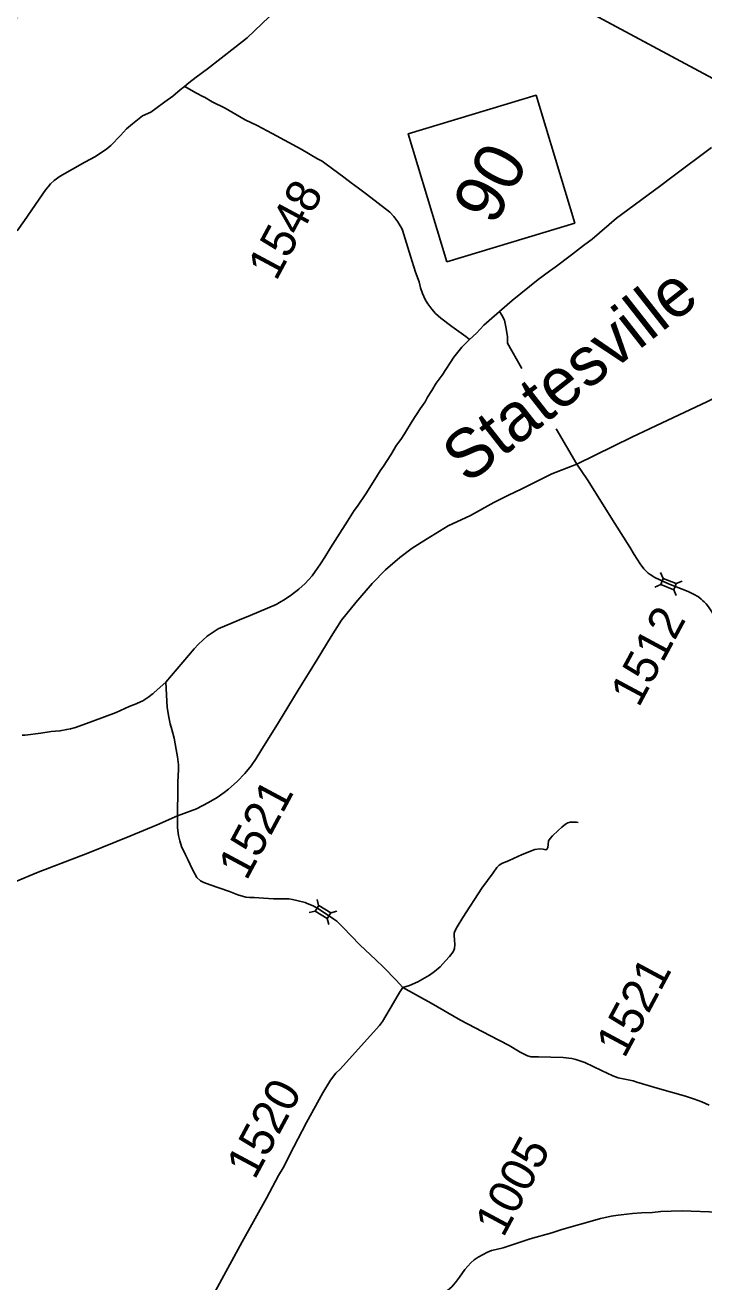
# Model space of a CAD drawing. Extents: x 1376167 to 1379209, y 761324 to 763997.
# Drawn here: x 1376608.1 to 1376691.6, y 762860.1 to 763014.5 of the extents above; entities that cross this region are included whole.
import ezdxf

# ---------------------------------------------------------------- set-up
doc = ezdxf.new("R2010")
doc.units = 0
for name, color, linetype in [('Default', 7, 'Continuous'), ('Old_Level_1', 7, 'Continuous'), ('Sheet Data Field CELL', 7, 'Continuous')]:
    doc.layers.add(name, color=color, linetype=linetype)

msp = doc.modelspace()

# ---------------------------------------------------------------- linework, layer by layer
at = {"layer": 'Default'}
for p, q in [((1376671.18, 762983.24), (1376672.6, 762984.28)), ((1376667.99, 762980.66), (1376671.18, 762983.24)), ((1376666.42, 762979.32), (1376667.99, 762980.66)), ((1376662.5, 762976.1), (1376662.31, 762976.25)), ((1376662.74, 762975.9), (1376662.5, 762976.1)), ((1376677.25, 762958.65), (1376675.94, 762960.58)), ((1376680.6, 762953.27), (1376677.25, 762958.65)), ((1376686.55, 762946.51), (1376686.24, 762947.23)), ((1376686.25, 762945.78), (1376685.53, 762945.46)), ((1376688.17, 762944.41), (1376687.86, 762945.13)), ((1376688.88, 762946.19), (1376688.16, 762945.88)), ((1376644.2, 762906.31), (1376644.02, 762907.08)), ((1376643.79, 762905.64), (1376643.02, 762905.45)), ((1376645.45, 762903.97), (1376645.26, 762904.73)), ((1376646.45, 762905.61), (1376645.69, 762905.42))]:
    msp.add_line(p, q, dxfattribs=at)
for points in [[(1376648.76, 763029.08), (1376648.29, 763028.55), (1376648, 763028.24), (1376647.83, 763028.06), (1376646.1, 763025.98), (1376643.79, 763022.92), (1376642.92, 763021.74), (1376641.74, 763020.29), (1376640.75, 763018.98), (1376640.14, 763018.1), (1376639.06, 763016.64), (1376638.1, 763015.54), (1376635.43, 763012.95), (1376633.91, 763011.77), (1376630.52, 763009.14), (1376629.15, 763008.11), (1376628.26, 763007.42), (1376627.71, 763006.98)], [(1376627.71, 763006.98), (1376627.16, 763006.56), (1376626.28, 763005.8), (1376625.29, 763005.09), (1376624.2, 763004.26), (1376623.57, 763003.82), (1376622.54, 763003.36), (1376621.31, 763002.38), (1376620.6, 763001.76), (1376619.85, 763000.97), (1376618.64, 762999.74), (1376618.16, 762999.32), (1376616.75, 762998.37), (1376615.46, 762997.66), (1376612.44, 762995.95), (1376611.69, 762995.44), (1376611.25, 762995.02), (1376610.96, 762994.64), (1376610.68, 762994.3), (1376608.02, 762990.52), (1376607.13, 762989.22)], [(1376630.03, 763005.72), (1376629.12, 763006.19), (1376628.04, 763006.81), (1376627.71, 763006.98)], [(1376632.69, 763004.31), (1376631.13, 763005.11), (1376630.17, 763005.65), (1376630.03, 763005.72)], [(1376635.15, 763002.87), (1376632.69, 763004.31)], [(1376644.07, 762998.1), (1376642.06, 762999.26), (1376638.5, 763001.2), (1376636.66, 763002.19), (1376635.15, 763002.87)], [(1376672.6, 762984.28), (1376673.27, 762984.79), (1376675.3, 762986.31), (1376676.78, 762987.43), (1376677.83, 762988.21), (1376680.82, 762990.8), (1376686.12, 762994.69), (1376687.79, 762995.97), (1376692.48, 762999.48)], [(1376647.29, 762995.82), (1376645.14, 762997.43), (1376644.62, 762997.79), (1376644.07, 762998.1)], [(1376658.57, 762979.07), (1376658.1, 762979.63), (1376657.62, 762980.26), (1376657.28, 762980.81), (1376656.95, 762981.55), (1376656.73, 762982.24), (1376656.54, 762982.96), (1376656.1, 762984.16), (1376655.51, 762986.12), (1376654.5, 762989.33), (1376654.35, 762989.67), (1376654.22, 762989.85), (1376653.94, 762990.35), (1376653.43, 762991.02), (1376652.96, 762991.52), (1376650.08, 762993.74), (1376649.09, 762994.49), (1376648.19, 762995.12), (1376647.29, 762995.82)], [(1376675.94, 762960.58), (1376682.69, 762963.88), (1376684.96, 762964.96), (1376691.99, 762968.25), (1376694.26, 762969.38), (1376696.28, 762970.78), (1376697.97, 762972.31), (1376699.64, 762974.04), (1376700.98, 762975.67), (1376702.88, 762978.32), (1376704.6, 762980.94), (1376709.52, 762988.1), (1376712.73, 762992.97), (1376713.7, 762994.26)], [(1376662.31, 762976.25), (1376660.58, 762977.5), (1376659.22, 762978.49), (1376658.57, 762979.07)], [(1376662.74, 762975.9), (1376663.59, 762976.68), (1376664.53, 762977.64), (1376665.16, 762978.23), (1376666.42, 762979.32)], [(1376667.43, 762975.44), (1376667.4, 762976.25), (1376667.2, 762977.44), (1376667.04, 762978.25), (1376666.73, 762978.88), (1376666.42, 762979.32)], [(1376657.28, 762968.22), (1376657.59, 762968.8), (1376658.11, 762969.62), (1376658.66, 762970.5), (1376659.39, 762971.52), (1376660.82, 762973.71), (1376661.8, 762974.94), (1376662.74, 762975.9)], [(1376669.17, 762972.32), (1376667.43, 762975.44)], [(1376654.75, 762964.28), (1376655.72, 762965.83), (1376656.7, 762967.35), (1376657.28, 762968.22)], [(1376675.94, 762960.58), (1376673.42, 762964.91)], [(1376648.57, 762954.88), (1376648.99, 762955.42), (1376649.99, 762956.92), (1376651.09, 762958.66), (1376651.76, 762959.75), (1376652.17, 762960.31), (1376653.06, 762961.71), (1376653.79, 762962.89), (1376654.31, 762963.59), (1376654.75, 762964.28)], [(1376665.72, 762955.85), (1376667.56, 762956.74), (1376669.11, 762957.49), (1376671.06, 762958.46), (1376672.88, 762959.36), (1376675.94, 762960.58)], [(1376650.79, 762945.89), (1376652.43, 762947.59), (1376654.2, 762949.11), (1376655.71, 762950.23), (1376657.46, 762951.36), (1376660.11, 762952.99), (1376662.89, 762954.26), (1376665.72, 762955.85)], [(1376645.64, 762950.29), (1376646.51, 762951.62), (1376647.76, 762953.57), (1376648.57, 762954.88)], [(1376687.2, 762945.84), (1376685.53, 762946.62), (1376684.95, 762947.01), (1376684.73, 762947.17), (1376684.18, 762947.72), (1376683.73, 762948.31), (1376683, 762949.47), (1376682.47, 762950.38), (1376680.6, 762953.27)], [(1376625.4, 762933.77), (1376628.88, 762937.86), (1376629.45, 762938.46), (1376630.49, 762939.41), (1376631.1, 762939.85), (1376631.86, 762940.34), (1376634.48, 762941.43), (1376635.8, 762941.96), (1376638.97, 762943.3), (1376639.38, 762943.56), (1376640.09, 762943.98), (1376640.85, 762944.49), (1376641.75, 762945.22), (1376642.54, 762945.88), (1376643.42, 762946.82), (1376644.43, 762948.3), (1376644.97, 762949.13), (1376645.64, 762950.29)], [(1376626.85, 762917.34), (1376629.17, 762918.2), (1376630.68, 762918.97), (1376631.71, 762919.59), (1376632.6, 762920.21), (1376633.11, 762920.63), (1376634.19, 762921.56), (1376635.14, 762922.54), (1376635.92, 762923.5), (1376636.53, 762924.38), (1376637.11, 762925.32), (1376639.26, 762928.8), (1376641.7, 762932.8), (1376644, 762936.56), (1376645.76, 762939.39), (1376647.02, 762941.39), (1376648.77, 762943.55), (1376650.79, 762945.89)], [(1376698.1, 762935.36), (1376697.04, 762935.8), (1376696.37, 762936.16), (1376695.83, 762936.5), (1376695.33, 762936.88), (1376694.89, 762937.34), (1376694.52, 762937.85), (1376693.82, 762939.14), (1376693.32, 762940.63), (1376693.1, 762941.29), (1376692.94, 762941.66), (1376692.52, 762942.42), (1376692.15, 762943.04), (1376691.86, 762943.38), (1376691.61, 762943.63), (1376691.41, 762943.82), (1376691.23, 762943.99), (1376690.89, 762944.24), (1376690.28, 762944.6), (1376689.62, 762944.92), (1376687.2, 762945.84)], [(1376607.74, 762927.24), (1376608.14, 762927.26), (1376610.03, 762927.5), (1376611.33, 762927.7), (1376612.39, 762927.79), (1376613.23, 762927.96), (1376613.71, 762928.04), (1376614.31, 762928.19), (1376616.43, 762928.98), (1376619.31, 762930.05), (1376620.92, 762930.8), (1376621.44, 762930.97), (1376621.57, 762931.04), (1376622.59, 762931.49), (1376623.33, 762931.97), (1376623.72, 762932.31), (1376623.8, 762932.35), (1376623.98, 762932.49), (1376625.4, 762933.77)], [(1376625.4, 762933.77), (1376625.59, 762930.66), (1376625.77, 762929.46), (1376625.95, 762928.67), (1376626.14, 762927.97), (1376626.42, 762926.89), (1376626.67, 762925.5), (1376626.85, 762924.6), (1376626.98, 762923.61), (1376626.98, 762923.11), (1376626.97, 762923.02), (1376626.91, 762921.49), (1376626.89, 762921.07), (1376626.91, 762919.7)], [(1376626.91, 762919.7), (1376626.84, 762918.43), (1376626.85, 762917.34)], [(1376599.4, 762907.2), (1376600.43, 762907.36), (1376602.2, 762907.68), (1376603.65, 762908.07), (1376605.17, 762908.52), (1376606.97, 762909.27), (1376609.74, 762910.44), (1376615.81, 762912.77), (1376621, 762914.85), (1376624.37, 762916.24), (1376626.85, 762917.34)], [(1376626.85, 762917.34), (1376626.83, 762916.51), (1376626.84, 762915.89), (1376626.97, 762914.92), (1376627.13, 762914.27)], [(1376654.57, 762896.26), (1376655.37, 762896.5), (1376656.41, 762896.96), (1376657.83, 762897.75), (1376658.46, 762898.22), (1376659.14, 762898.8), (1376659.81, 762899.53), (1376660.27, 762900.04), (1376660.76, 762900.64), (1376660.91, 762901.02), (1376660.92, 762901.12), (1376660.94, 762901.46), (1376660.89, 762902.17), (1376660.87, 762902.54), (1376660.86, 762902.91), (1376660.95, 762903.18), (1376661.22, 762903.72), (1376661.91, 762904.86), (1376664.27, 762908.45), (1376665.64, 762910.35), (1376666.11, 762910.99), (1376666.39, 762911.27), (1376666.74, 762911.47), (1376667.64, 762911.87), (1376669.24, 762912.61), (1376670.76, 762913.2), (1376671.4, 762913.28), (1376671.8, 762913.25), (1376672.15, 762913.18), (1376672.29, 762913.27), (1376672.36, 762913.47), (1376672.41, 762913.84), (1376672.48, 762914.28), (1376672.65, 762914.56), (1376672.96, 762914.87), (1376673.65, 762915.53), (1376674.11, 762915.94), (1376674.57, 762916.33), (1376674.82, 762916.47), (1376675.12, 762916.55), (1376675.51, 762916.55), (1376675.92, 762916.55), (1376676.1, 762916.54)], [(1376627.13, 762914.27), (1376627.35, 762913.59), (1376627.82, 762912.54), (1376628.16, 762911.9), (1376628.41, 762911.37), (1376628.69, 762910.76), (1376629.24, 762909.77), (1376629.66, 762909.37), (1376630.09, 762909.15), (1376630.86, 762908.88), (1376631.94, 762908.51), (1376633.25, 762908.04), (1376634.25, 762907.62), (1376635.26, 762907.36), (1376635.71, 762907.32), (1376636.29, 762907.29), (1376637.41, 762907.24), (1376638.66, 762907.13), (1376640.53, 762907.15), (1376640.97, 762907.07), (1376641.52, 762906.95), (1376642.54, 762906.7), (1376642.79, 762906.59)], [(1376642.79, 762906.59), (1376643.51, 762906.29), (1376644.32, 762905.83), (1376644.73, 762905.54)], [(1376644.73, 762905.54), (1376645.41, 762905.1), (1376646.08, 762904.65), (1376646.42, 762904.39), (1376647.18, 762903.66), (1376649.27, 762901.51), (1376651.23, 762899.64), (1376652.18, 762898.73), (1376653.74, 762897.13), (1376654.57, 762896.26)], [(1376644.7, 762883.3), (1376645.64, 762884.85), (1376646.32, 762885.72), (1376646.86, 762886.23), (1376651.69, 762891.57), (1376652.05, 762892.07), (1376653.39, 762894.36), (1376654.15, 762895.64), (1376654.57, 762896.26)], [(1376654.57, 762896.26), (1376658.04, 762894.31), (1376661.66, 762892.22), (1376665.23, 762890.33), (1376667.61, 762889.1), (1376668.96, 762888.3), (1376669.86, 762887.84), (1376670.31, 762887.71), (1376671.23, 762887.74), (1376674.27, 762887.65), (1376675.32, 762887.53), (1376675.81, 762887.41), (1376676.93, 762887.03), (1376678.96, 762886.03), (1376680.37, 762885.4), (1376681.04, 762885.15), (1376682.88, 762884.78), (1376683.3, 762884.63), (1376686.11, 762883.78), (1376689.31, 762882.9), (1376690.39, 762882.54), (1376691.32, 762882.19), (1376692.22, 762881.79)], [(1376642.18, 762878.63), (1376642.7, 762879.65), (1376644.7, 762883.3)], [(1376631.28, 762858.51), (1376634.78, 762864.99), (1376637.78, 762870.34), (1376639.28, 762873.13), (1376639.82, 762874.1), (1376641.16, 762876.68), (1376642.18, 762878.63)], [(1376670.21, 762865.34), (1376672.85, 762866.1), (1376674.08, 762866.51), (1376678.46, 762867.73), (1376678.84, 762867.85)], [(1376678.84, 762867.85), (1376679.28, 762867.96), (1376680.15, 762868.14), (1376681.03, 762868.27), (1376681.4, 762868.29)], [(1376681.4, 762868.29), (1376682.77, 762868.46), (1376683.88, 762868.54)], [(1376683.88, 762868.54), (1376685.24, 762868.61), (1376686.28, 762868.7), (1376687.54, 762868.74), (1376688.9, 762868.78)], [(1376688.9, 762868.78), (1376693.37, 762868.65), (1376698.5, 762868.56)], [(1376656.18, 762856.74), (1376658.93, 762858.21), (1376659.77, 762858.78), (1376660.56, 762859.46), (1376660.74, 762859.67), (1376661.01, 762860), (1376661.51, 762860.66), (1376662.19, 762861.6), (1376662.92, 762862.41), (1376663.31, 762862.78), (1376663.82, 762863.12), (1376664.42, 762863.44), (1376664.87, 762863.68), (1376665.46, 762863.92), (1376666.03, 762864.06), (1376666.87, 762864.24), (1376670.21, 762865.34)]]:
    msp.add_lwpolyline(points, dxfattribs=at)
for points in [[(1376659.96, 762985.44), (1376655.21, 763001.17), (1376670.93, 763005.91), (1376675.68, 762990.19)], [(1376687.86, 762945.13), (1376686.25, 762945.77), (1376686.55, 762946.52), (1376688.16, 762945.88)], [(1376645.26, 762904.73), (1376643.79, 762905.63), (1376644.21, 762906.32), (1376645.69, 762905.42)]]:
    msp.add_lwpolyline(points, close=True, dxfattribs=at)
at = {"layer": 'Old_Level_1'}
for points in [[(1376622.61, 762553.05), (1376345.79, 762701.47), (1376550.88, 763083.99), (1376827.7, 762935.57)], [(1376345.79, 762701.47), (1376660.36, 762532.81), (1376865.45, 762915.33), (1376550.88, 763083.99)]]:
    msp.add_lwpolyline(points, close=True, dxfattribs=at)

# ---------------------------------------------------------------- texts
at = {"layer": 'Default'}
for s, height, rotation, p in [('90', 6.103, 61.8015, (1376665.8, 762989.72)), ('Statesville', 6, 38.1304, (1376662.49, 762958.01))]:
    msp.add_text(s, height=height, rotation=rotation, dxfattribs=at).set_placement(p)
at = {"layer": 'Old_Level_1'}
for s, p in [('1548', (1376638.98, 762982.96)), ('1512', (1376683.55, 762930.55)), ('1521', (1376635.34, 762909.27)), ('1521', (1376681.79, 762887.42)), ('1520', (1376636.34, 762872.5)), ('1005', (1376666.9, 762865.41))]:
    msp.add_text(s, height=4.185, rotation=61.8015, dxfattribs=at).set_placement(p)
at = {"layer": 'Sheet Data Field CELL'}
msp.add_text('          ALEXANDER          ', height=30, rotation=61.6702, dxfattribs=at).set_placement((1376533.71, 762878.93))

doc.saveas('drawing.dxf')
